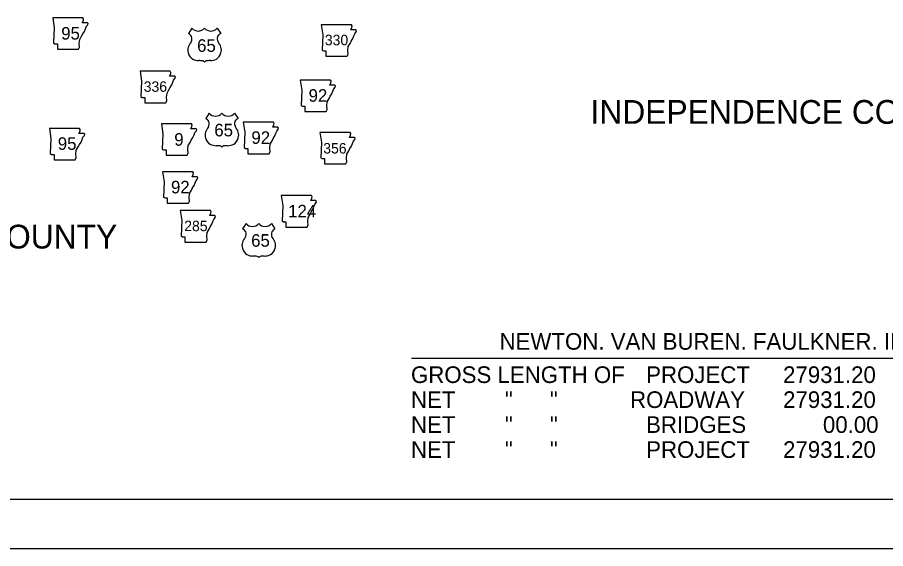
# Model space of a CAD drawing. Extents: x 840176 to 859715, y 1589036 to 1600368.
# Drawn here: x 844826 to 849210, y 1589036 to 1591717 of the extents above; entities that cross this region are included whole.
import ezdxf

# ---------------------------------------------------------------- set-up
doc = ezdxf.new("R2010")
doc.units = 0
for name, color, linetype in [('Default', 7, 'Continuous'), ('DSN_DRFT_Border', 7, 'Continuous'), ('SHET_Border-Text', 7, 'Continuous')]:
    doc.layers.add(name, color=color, linetype=linetype)

msp = doc.modelspace()

# ---------------------------------------------------------------- linework, layer by layer
at = {"layer": 'Default'}
for p, q in [((845706.7, 1591662.9), (845689.4, 1591636.1)), ((845835.4, 1591662.9), (845852.7, 1591636.1)), ((845794.1, 1591233.7), (845776.8, 1591207)), ((845922.8, 1591233.7), (845940.1, 1591207)), ((845980.4, 1590676.6), (845963.1, 1590649.8)), ((846109, 1590676.6), (846126.4, 1590649.8))]:
    msp.add_line(p, q, dxfattribs=at)
for points in [[(845004.4, 1591715.5), (845012, 1591664.8), (845008.6, 1591587.8), (845015.4, 1591583.6), (845028.1, 1591583.6), (845028.1, 1591556.5), (845134.7, 1591556.5), (845139.7, 1591567.5), (845138, 1591585.3), (845140.6, 1591605.6), (845149.9, 1591621.6), (845155.8, 1591633.5), (845164.3, 1591646.2), (845169.3, 1591659.7), (845173.6, 1591670.7), (845181.2, 1591680), (845182.9, 1591685.9), (845179.5, 1591690.1), (845153.3, 1591690.1), (845159.2, 1591702), (845160, 1591709.6), (845156.5, 1591715.4)], [(846360.3, 1591679.5), (846368, 1591628.7), (846364.6, 1591551.8), (846371.3, 1591547.5), (846384, 1591547.5), (846384, 1591520.5), (846490.6, 1591520.5), (846495.7, 1591531.5), (846494, 1591549.2), (846496.5, 1591569.5), (846505.8, 1591585.6), (846511.8, 1591597.4), (846520.2, 1591610.1), (846525.3, 1591623.7), (846529.5, 1591634.7), (846537.1, 1591644), (846538.8, 1591649.9), (846535.4, 1591654.1), (846509.2, 1591654.1), (846515.1, 1591666), (846516, 1591673.6), (846512.5, 1591679.4)], [(845445.5, 1591445.3), (845453.1, 1591394.6), (845449.8, 1591317.6), (845456.5, 1591313.4), (845469.2, 1591313.4), (845469.2, 1591286.3), (845575.8, 1591286.3), (845580.9, 1591297.3), (845579.2, 1591315), (845581.7, 1591335.3), (845591, 1591351.4), (845596.9, 1591363.3), (845605.4, 1591375.9), (845610.5, 1591389.5), (845614.7, 1591400.5), (845622.3, 1591409.8), (845624, 1591415.7), (845620.6, 1591419.9), (845594.4, 1591419.9), (845600.3, 1591431.8), (845601.2, 1591439.4), (845597.7, 1591445.2)], [(846254.3, 1591400.8), (846261.9, 1591350), (846258.5, 1591273.1), (846265.3, 1591268.8), (846277.9, 1591268.8), (846277.9, 1591241.8), (846384.5, 1591241.8), (846389.6, 1591252.8), (846387.9, 1591270.5), (846390.5, 1591290.8), (846399.8, 1591306.9), (846405.7, 1591318.7), (846414.1, 1591331.4), (846419.2, 1591345), (846423.4, 1591355.9), (846431.1, 1591365.3), (846432.7, 1591371.2), (846429.4, 1591375.4), (846403.1, 1591375.4), (846409.1, 1591387.2), (846409.9, 1591394.9), (846406.4, 1591400.7)], [(845966.4, 1591187.8), (845974, 1591137.1), (845970.6, 1591060.1), (845977.4, 1591055.9), (845990.1, 1591055.9), (845990.1, 1591028.8), (846096.7, 1591028.8), (846101.7, 1591039.8), (846100, 1591057.6), (846102.6, 1591077.9), (846111.9, 1591094), (846117.8, 1591105.8), (846126.3, 1591118.5), (846131.3, 1591132), (846135.6, 1591143), (846143.2, 1591152.3), (846144.9, 1591158.2), (846141.5, 1591162.5), (846115.3, 1591162.5), (846121.2, 1591174.3), (846122, 1591181.9), (846118.5, 1591187.8)], [(844987.2, 1591157), (844994.8, 1591106.3), (844991.4, 1591029.3), (844998.2, 1591025.1), (845010.8, 1591025.1), (845010.8, 1590998), (845117.4, 1590998), (845122.5, 1591009), (845120.8, 1591026.8), (845123.3, 1591047.1), (845132.7, 1591063.1), (845138.6, 1591075), (845147, 1591087.7), (845152.1, 1591101.2), (845156.3, 1591112.2), (845164, 1591121.5), (845165.6, 1591127.4), (845162.3, 1591131.7), (845136, 1591131.7), (845142, 1591143.5), (845142.8, 1591151.1), (845139.3, 1591157)], [(845552.7, 1591180.1), (845560.3, 1591129.3), (845557, 1591052.4), (845563.7, 1591048.1), (845576.4, 1591048.1), (845576.4, 1591021.1), (845683, 1591021.1), (845688.1, 1591032.1), (845686.4, 1591049.8), (845688.9, 1591070.1), (845698.2, 1591086.2), (845704.1, 1591098), (845712.6, 1591110.7), (845717.7, 1591124.3), (845721.9, 1591135.3), (845729.5, 1591144.6), (845731.2, 1591150.5), (845727.8, 1591154.7), (845701.6, 1591154.7), (845707.5, 1591166.6), (845708.4, 1591174.2), (845704.9, 1591180)], [(846353.5, 1591136.7), (846361.1, 1591085.9), (846357.7, 1591008.9), (846364.5, 1591004.7), (846377.1, 1591004.7), (846377.1, 1590977.6), (846483.7, 1590977.6), (846488.8, 1590988.6), (846487.1, 1591006.4), (846489.7, 1591026.7), (846499, 1591042.8), (846504.9, 1591054.6), (846513.3, 1591067.3), (846518.4, 1591080.8), (846522.6, 1591091.8), (846530.3, 1591101.1), (846531.9, 1591107.1), (846528.6, 1591111.3), (846502.3, 1591111.3), (846508.3, 1591123.1), (846509.1, 1591130.7), (846505.6, 1591136.6)], [(845558.8, 1590938.1), (845566.5, 1590887.4), (845563.1, 1590810.4), (845569.8, 1590806.1), (845582.5, 1590806.1), (845582.5, 1590779.1), (845689.1, 1590779.1), (845694.2, 1590790.1), (845692.5, 1590807.8), (845695, 1590828.1), (845704.3, 1590844.2), (845710.3, 1590856.1), (845718.7, 1590868.7), (845723.8, 1590882.3), (845728, 1590893.3), (845735.6, 1590902.6), (845737.3, 1590908.5), (845733.9, 1590912.7), (845707.7, 1590912.7), (845713.6, 1590924.6), (845714.5, 1590932.2), (845711, 1590938)], [(846158.2, 1590817.6), (846165.9, 1590766.8), (846162.5, 1590689.9), (846169.2, 1590685.6), (846181.9, 1590685.6), (846181.9, 1590658.6), (846288.5, 1590658.6), (846293.6, 1590669.6), (846291.9, 1590687.3), (846294.4, 1590707.6), (846303.7, 1590723.7), (846309.7, 1590735.6), (846318.1, 1590748.2), (846323.2, 1590761.8), (846327.4, 1590772.8), (846335, 1590782.1), (846336.7, 1590788), (846333.3, 1590792.2), (846307.1, 1590792.2), (846313, 1590804.1), (846313.9, 1590811.7), (846310.4, 1590817.5)], [(845648.5, 1590742.1), (845656.1, 1590691.4), (845652.7, 1590614.4), (845659.5, 1590610.1), (845672.2, 1590610.1), (845672.2, 1590583.1), (845778.8, 1590583.1), (845783.8, 1590594.1), (845782.1, 1590611.8), (845784.7, 1590632.1), (845794, 1590648.2), (845799.9, 1590660.1), (845808.4, 1590672.7), (845813.4, 1590686.3), (845817.7, 1590697.3), (845825.3, 1590706.6), (845827, 1590712.5), (845823.6, 1590716.7), (845797.4, 1590716.7), (845803.3, 1590728.6), (845804.1, 1590736.2), (845800.6, 1590742)]]:
    msp.add_lwpolyline(points, close=True, dxfattribs=at)
for centre, radius, start, end in [((845666.8, 1591597.3), 45, 30.7809, 59.9883), ((845676.7, 1591609.1), 30.8, 328.8105, 21.2108), ((845738.9, 1591690), 42.1, 220.075, 319.6701), ((845803.1, 1591690), 42.1, 220.3299, 319.925), ((845865.4, 1591609.1), 30.8, 158.7892, 211.1895), ((845875.3, 1591597.3), 45, 120.0117, 149.2191), ((845757.3, 1591545.9), 71.9, 138.9565, 162.6913), ((845784.8, 1591545.9), 71.9, 17.3087, 41.0435), ((845733.5, 1591551.8), 47.5, 160.9576, 197.3819), ((845741.3, 1591552), 55, 195.1074, 237.1312), ((845800.8, 1591552), 55, 302.8688, 344.8926), ((845808.5, 1591551.8), 47.5, 342.6181, 19.0424), ((845742.3, 1591569.3), 70.6, 244.0771, 269.5779), ((845743.9, 1591369.4), 129.3, 81.1942, 90.9539), ((845760.1, 1591485.3), 12.4, 28.0342, 72.9864), ((845782, 1591485.3), 12.4, 107.0136, 151.9658), ((845798.1, 1591369.4), 129.3, 89.0461, 98.8058), ((845799.8, 1591569.3), 70.6, 270.4221, 295.9229), ((845826.3, 1591260.8), 42.1, 220.075, 319.6701), ((845890.5, 1591260.8), 42.1, 220.3299, 319.925), ((845754.1, 1591168.1), 45, 30.7809, 59.9883), ((845764, 1591180), 30.8, 328.8105, 21.2108), ((845952.8, 1591180), 30.8, 158.7892, 211.1895), ((845962.7, 1591168.1), 45, 120.0117, 149.2191), ((845820.9, 1591122.7), 47.5, 160.9576, 197.3819), ((845844.6, 1591116.8), 71.9, 138.9565, 162.6913), ((845872.2, 1591116.8), 71.9, 17.3087, 41.0435), ((845895.9, 1591122.7), 47.5, 342.6181, 19.0424), ((845828.6, 1591122.8), 55, 195.1074, 237.1312), ((845888.2, 1591122.8), 55, 302.8688, 344.8926), ((845829.7, 1591140.1), 70.6, 244.0771, 269.5779), ((845831.3, 1590940.2), 129.3, 81.1942, 90.9539), ((845847.5, 1591056.2), 12.4, 28.0342, 72.9864), ((845869.4, 1591056.2), 12.4, 107.0136, 151.9658), ((845885.5, 1590940.2), 129.3, 89.0461, 98.8058), ((845887.2, 1591140.1), 70.6, 270.4221, 295.9229), ((846012.6, 1590703.7), 42.1, 220.075, 319.6701), ((846076.8, 1590703.7), 42.1, 220.3299, 319.925), ((845940.4, 1590611), 45, 30.7809, 59.9883), ((845950.3, 1590622.8), 30.8, 328.8105, 21.2108), ((846139.1, 1590622.8), 30.8, 158.7892, 211.1895), ((846149, 1590611), 45, 120.0117, 149.2191), ((846007.2, 1590565.5), 47.5, 160.9576, 197.3819), ((846030.9, 1590559.7), 71.9, 138.9565, 162.6913), ((846058.5, 1590559.7), 71.9, 17.3087, 41.0435), ((846082.2, 1590565.5), 47.5, 342.6181, 19.0424), ((846014.9, 1590565.7), 55, 195.1074, 237.1312), ((846074.5, 1590565.7), 55, 302.8688, 344.8926), ((846016, 1590583), 70.6, 244.0771, 269.5779), ((846017.6, 1590383.1), 129.3, 81.1942, 90.9539), ((846033.8, 1590499), 12.4, 28.0342, 72.9864), ((846055.6, 1590499), 12.4, 107.0136, 151.9658), ((846071.8, 1590383.1), 129.3, 89.0461, 98.8058), ((846073.4, 1590583), 70.6, 270.4221, 295.9229)]:
    msp.add_arc(centre, radius, start, end, dxfattribs=at)
at = {"layer": 'DSN_DRFT_Border'}
msp.add_line((846815.5, 1589997.6), (850535.5, 1589997.6), dxfattribs=at)
msp.add_lwpolyline([(840175.5, 1600035.6), (840175.5, 1589035.6), (857175.5, 1589035.6), (857175.5, 1600035.6)], close=True, dxfattribs=at)
at = {"layer": 'SHET_Border-Text'}
for points in [[(840175.5, 1589035.6), (857175.5, 1589035.6), (857175.5, 1600035.6), (840175.5, 1600035.6)], [(840425.5, 1589285.6), (856925.5, 1589285.6), (856925.5, 1599785.6), (840425.5, 1599785.6)]]:
    msp.add_lwpolyline(points, close=True, dxfattribs=at)

# ---------------------------------------------------------------- texts
at = {"layer": 'Default'}
for s, height, p in [('95', 63.36, (845047.1, 1591604.8)), ('330', 52.8, (846378.5, 1591576.5)), ('65', 63.36, (845733.4, 1591543.3)), ('336', 52.8, (845463.7, 1591341.3)), ('92', 63.36, (846296.4, 1591291.2)), ('65', 63.36, (845820.3, 1591116.5)), ('92', 63.36, (846007.7, 1591078.6)), ('95', 63.36, (845029.9, 1591048.4)), ('9', 63.4, (845618.1, 1591069.3)), ('356', 52.8, (846370.4, 1591029.9)), ('92', 63.36, (845601.5, 1590828.7)), ('124', 63.36, (846193.2, 1590707.5)), ('285', 52.8, (845668.4, 1590638)), ('65', 63.36, (846006.3, 1590559.5))]:
    msp.add_text(s, height=height, dxfattribs=at).set_placement(p)
at = {"layer": 'DSN_DRFT_Border'}
for s, height, p in [('INDEPENDENCE COUNTY', 120, (847720.2, 1591179.8)), ('VAN BUREN COUNTY', 120, (843671.6, 1590550.4)), ('NEWTON. VAN BUREN. FAULKNER. INDEPENDENCE. ', 84, (847260.6, 1590039.6)), ('GROSS LENGTH OF', 84, (846813.4, 1589871.6)), ('PROJECT', 84, (848001.1, 1589871.6)), ('27931.20', 84, (848692.5, 1589871.6)), ('NET        "      "', 84, (846813.4, 1589745.6)), ('ROADWAY', 84, (847919.7, 1589745.6)), ('27931.20', 84, (848692.5, 1589745.6)), ('NET        "      "', 84, (846813.4, 1589619.6)), ('BRIDGES', 84, (848000.7, 1589619.6)), ('00.00', 84, (848893.8, 1589619.6)), ('NET        "      "', 84, (846813.4, 1589493.6)), ('PROJECT', 84, (848001.1, 1589493.6)), ('27931.20', 84, (848692.5, 1589493.6))]:
    msp.add_text(s, height=height, dxfattribs=at).set_placement(p)

doc.saveas('drawing.dxf')
